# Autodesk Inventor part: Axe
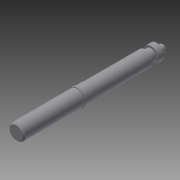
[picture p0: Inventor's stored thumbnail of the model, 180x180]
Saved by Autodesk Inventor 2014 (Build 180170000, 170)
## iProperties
Created: 2015-07
Part Number: Axe
Material: Générique
Document SubType Name: Modeling
Designer: OL
Density: 1 g/cm^3
Appearance: Par défaut
Author: OL
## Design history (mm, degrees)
sketch "Esquisse1"
  geometry: L1 (0, 0)-(0, 27.5); L2 (0, 27.5)-(210, 27.5); L3 (210, 27.5)-(210, 30); L4 (210, 30)-(215, 30); L5 (245, 27.5)-(245, 26.5); L6 (245, 26.5)-(447, 26.5); L7 (447, 26.5)-(447, 20); L8 (447, 20)-(467, 20); L9 (467, 20)-(467, 26.5); L10 (467, 26.5)-(487, 26.5); L11 (487, 26.5)-(487, 12.5); L12 (487, 12.5)-(512, 12.5); L13 (512, 12.5)-(512, 0); L14 (512, 0)-(0, 0); L15 (245, 27.5)-(215, 27.5); L16 (215, 27.5)-(215, 30)
  constraints: 32 end point, 13 parallel, 2 perpendicular, 1 vertical
  dimensions: "d0" = 27.5 distance between parallel lines of L14 L2; "d2" = 512 distance of L13.end L1.start; "d3" = 30 distance between parallel lines of L14 L4; "d4" = 26.5 distance between parallel lines of L14 L6; "d5" = 20 distance between parallel lines of L14 L8; "d6" = 26.5 distance between parallel lines of L14 L10; "d7" = 12.5 distance between parallel lines of L14 L12; "d9" = 20 distance of L7.end L8.end; "d10" = 20 distance of L9.end L10.end; "d11" = 25 distance of L11.end L12.end; "d12" = 210 distance of L1.end L2.end; "d13" = 5 distance of L3.end L4.end; "d14" = 27.5 distance between parallel lines of L14 L15; "d15" = 30 distance of L5.start L15.end
revolve "Révolution1" sketch "Esquisse1" stored, may be unused: angle "d16" = 90 deg
chamfer "Chanfrein1" distance "d17" = 5; stored, may be unused: second distance "d18" = 2, angle "d19" = 45 deg
chamfer "Chanfrein2" distance "d20" = 5; stored, may be unused: second distance "d21" = 2, angle "d22" = 45 deg
node "Solide1"
